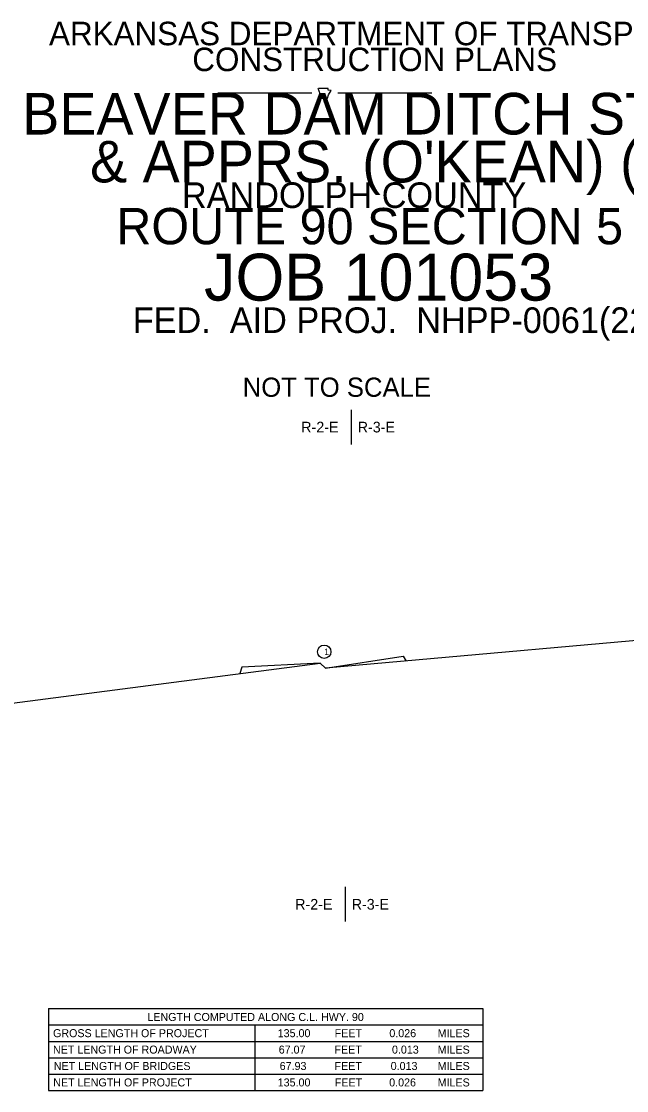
# Model space of a CAD drawing. Extents: x 166 to 3406, y 71 to 2074.
# Drawn here: x 1181 to 2316, y 71 to 2074 of the extents above; entities that cross this region are included whole.
import ezdxf

# ---------------------------------------------------------------- set-up
doc = ezdxf.new("R2010")
doc.units = 0
for name, color, linetype in [('1', 7, 'Continuous'), ('2', 7, 'Continuous'), ('3', 7, 'Continuous'), ('Default', 7, 'Continuous')]:
    doc.layers.add(name, color=color, linetype=linetype)

msp = doc.modelspace()

# ---------------------------------------------------------------- linework, layer by layer
at = {"layer": '1'}
for p, q in [((1549.3, 1940.2), (1725.4, 1940.2)), ((1774.4, 1940.2), (1950.5, 1940.2)), ((1751.4, 862), (1741.3, 871.7))]:
    msp.add_line(p, q, dxfattribs=at)
msp.add_lwpolyline([(1736.9, 1949.1), (1740.6, 1939.3), (1740.6, 1933.3), (1743.6, 1932.6), (1743.6, 1930.4), (1754.8, 1930.4), (1757, 1936.4), (1761.5, 1944.6), (1756.3, 1945.3), (1756.3, 1948.3), (1737.7, 1948.3)], dxfattribs=at)
at = {"layer": '2'}
msp.add_circle((1748.7, 893), 12.6, dxfattribs=at)
at = {"layer": '3'}
for p, q in [((1231.7, 224.3), (1231.7, 70.6)), ((1231.7, 224.3), (2046.2, 224.3)), ((2046.2, 224.3), (2046.2, 70.6)), ((1231.7, 193.6), (2046.2, 193.6)), ((1618.4, 193.6), (1618.4, 70.6)), ((1231.7, 162.8), (2046.2, 162.8)), ((1231.7, 132.1), (2046.2, 132.1)), ((1231.7, 101.3), (2046.2, 101.3)), ((1231.7, 70.6), (2046.2, 70.6))]:
    msp.add_line(p, q, dxfattribs=at)
at = {"layer": 'Default'}
for p, q in [((1799.5, 1346.4), (1799.5, 1281.4)), ((1788.2, 452.2), (1788.2, 387.2))]:
    msp.add_line(p, q, dxfattribs=at)
for points in [[(2523.8, 931.1), (1751.4, 862), (1897, 884.7), (1902.2, 875.5)], [(1032.9, 779.5), (1741.3, 871.7), (1594.2, 864.1), (1590.3, 852.1)]]:
    msp.add_lwpolyline(points, dxfattribs=at)

# ---------------------------------------------------------------- texts
at = {"layer": '2'}
for s, height, p in [('ARKANSAS DEPARTMENT OF TRANSPORTATION', 44.028, (1232.8, 2029.5)), ('CONSTRUCTION PLANS', 44.028, (1501.4, 1981)), ('BEAVER DAM DITCH STR.', 78, (1182.5, 1862.2)), ("& APPRS. (O'KEAN) (S)", 78, (1309.7, 1772.5)), ('RANDOLPH COUNTY', 48, (1482, 1724.5)), ('ROUTE 90 SECTION 5', 68, (1359, 1656.5)), ('JOB 101053', 88, (1523.5, 1550.9)), ('FED.  AID PROJ.  NHPP-0061(22)', 48, (1389.8, 1490.3)), ('NOT TO SCALE', 36, (1595.9, 1370.7)), ('1', 12, (1748.7, 887))]:
    msp.add_text(s, height=height, dxfattribs=at).set_placement(p)
at = {"layer": '3'}
for s, height, p in [('LENGTH COMPUTED ALONG C.L. HWY. 90', 15.001, (1417.2, 201)), ('GROSS LENGTH OF PROJECT', 15.001, (1240.3, 170.7)), ('135.00', 15, (1661.5, 170.7)), ('FEET', 15, (1768.2, 170.7)), ('0.026', 15, (1870.8, 170.7)), ('MILES', 15, (1961.3, 170.7)), ('NET LENGTH OF ROADWAY', 15.001, (1240.2, 139.9)), ('67.07', 15, (1663.4, 139.9)), ('FEET', 15, (1767.9, 139.9)), ('0.013', 15, (1875.7, 139.9)), ('MILES', 15, (1961.3, 139.9)), ('NET LENGTH OF BRIDGES', 15.001, (1241.7, 109.2)), ('67.93', 15, (1665.2, 109.2)), ('FEET', 15, (1768, 109.2)), ('0.013', 15, (1873.3, 109.2)), ('MILES', 15, (1961.3, 109.2)), ('NET LENGTH OF PROJECT', 15.001, (1240.7, 78.4)), ('135.00', 15, (1661.5, 78.4)), ('FEET', 15, (1768.5, 78.4)), ('0.026', 15, (1870.5, 78.4)), ('MILES', 15, (1961.3, 78.4))]:
    msp.add_text(s, height=height, dxfattribs=at).set_placement(p)
at = {"layer": 'Default'}
for s, p in [('R-2-E', (1705.6, 1303.9)), ('R-3-E', (1811.5, 1303.9)), ('R-2-E', (1694.3, 409.7)), ('R-3-E', (1800.2, 409.7))]:
    msp.add_text(s, height=20, dxfattribs=at).set_placement(p)

doc.saveas('drawing.dxf')
